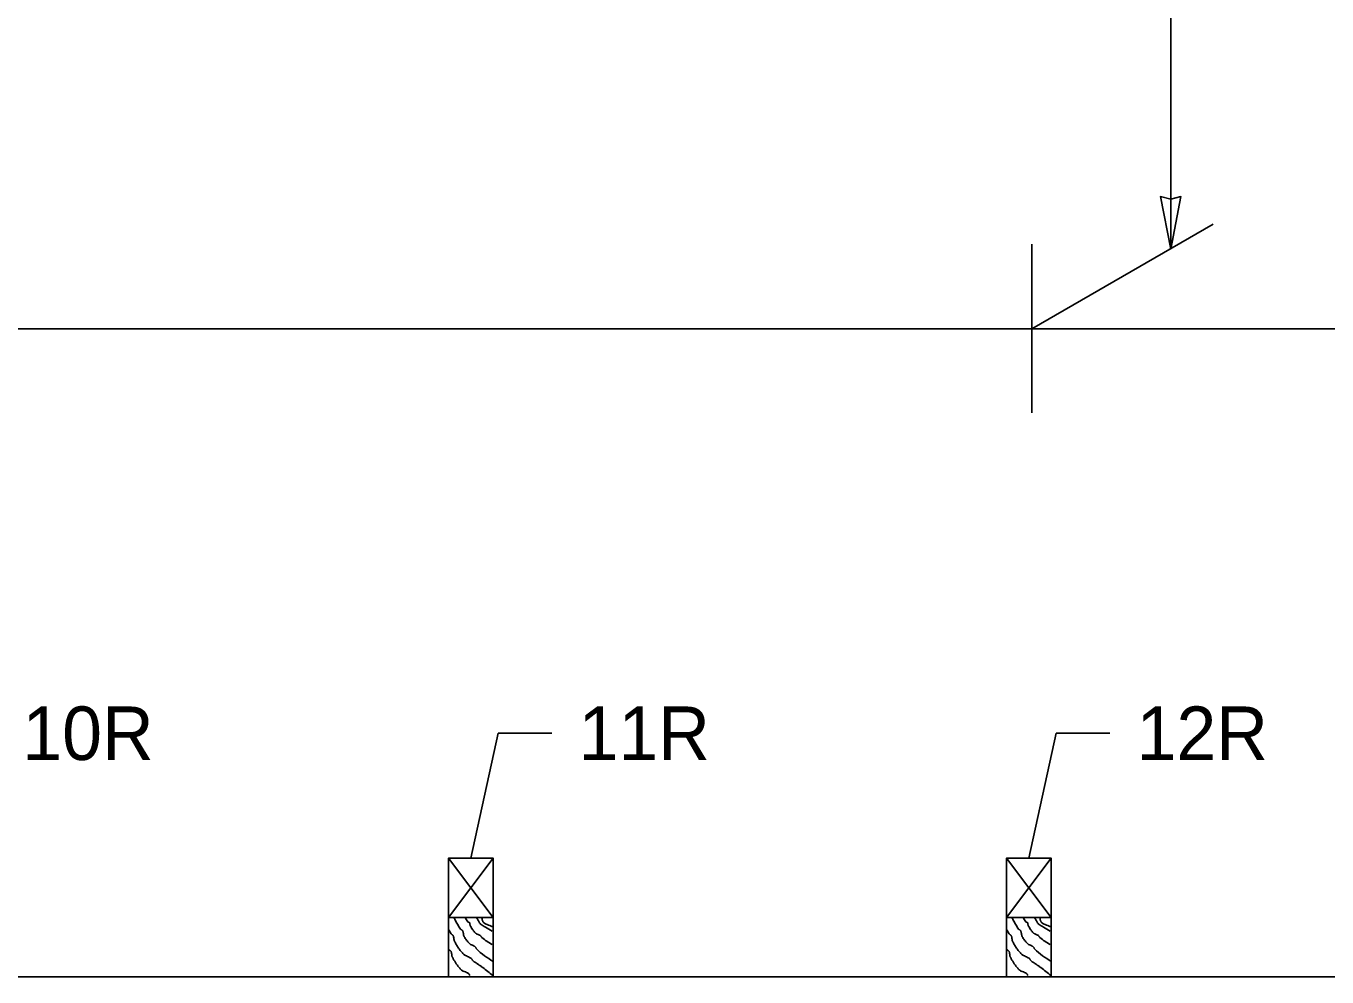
# Model space of a CAD drawing. Extents: x 1312564.2 to 1312581.5, y 1207298.4 to 1207352.6.
# Drawn here: x 1312571.742 to 1312573.678, y 1207306.026 to 1207307.442 of the extents above; entities that cross this region are included whole.
import ezdxf

# ---------------------------------------------------------------- set-up
doc = ezdxf.new("R2010")
doc.units = 0
for name, color, linetype in [('Level 13', 7, 'Continuous'), ('Level 14', 7, 'Continuous'), ('Level 15', 7, 'Continuous'), ('Level 20', 7, 'Continuous')]:
    doc.layers.add(name, color=color, linetype=linetype)

msp = doc.modelspace()

# ---------------------------------------------------------------- linework, layer by layer
at = {"layer": 'Level 13'}
for points in [[(1312572.3785139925, 1207306.1144906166), (1312572.3812686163, 1207306.1093584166), (1312572.3829368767, 1207306.1063364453), (1312572.3846655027, 1207306.1033469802), (1312572.3864358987, 1207306.1003835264), (1312572.388229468, 1207306.0974395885), (1312572.3885123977, 1207306.0970950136), (1312572.3888703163, 1207306.096820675), (1312572.3897133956, 1207306.0963912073), (1312572.3905632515, 1207306.0959681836), (1312572.3912244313, 1207306.0953686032), (1312572.391532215, 1207306.094851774), (1312572.391786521, 1207306.0943095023), (1312572.3921640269, 1207306.0931621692), (1312572.3925999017, 1207306.0907110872), (1312572.393001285, 1207306.0882319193), (1312572.393561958, 1207306.0864843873), (1312572.393837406, 1207306.0859412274), (1312572.3954116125, 1207306.0833483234), (1312572.397141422, 1207306.0808527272), (1312572.399039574, 1207306.0784748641), (1312572.4011188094, 1207306.0762351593), (1312572.4022092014, 1207306.07531773), (1312572.4034186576, 1207306.0745558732), (1312572.4060287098, 1207306.073294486), (1312572.408616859, 1207306.072042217), (1312572.4097989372, 1207306.0712917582), (1312572.4108509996, 1207306.0703902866), (1312572.4112330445, 1207306.0697751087), (1312572.4114778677, 1207306.0690462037), (1312572.4117438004, 1207306.068335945), (1312572.4121891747, 1207306.0677767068), (1312572.4370145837, 1207306.0492125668)], [(1312572.395383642, 1207306.1144906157), (1312572.3993067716, 1207306.1079405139), (1312572.3995254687, 1207306.1077062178), (1312572.39981993, 1207306.1075601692), (1312572.4005369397, 1207306.1074167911), (1312572.4012593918, 1207306.1072783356), (1312572.4017888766, 1207306.106912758), (1312572.40192999, 1207306.1066689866), (1312572.4020432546, 1207306.1064129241), (1312572.4022013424, 1207306.1058704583), (1312572.402349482, 1207306.1047099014), (1312572.4024749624, 1207306.1035356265), (1312572.4026047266, 1207306.102976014), (1312572.402819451, 1207306.102452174), (1312572.4036161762, 1207306.100979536), (1312572.4044412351, 1207306.0995169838), (1312572.4062161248, 1207306.096656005), (1312572.4093395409, 1207306.092651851), (1312572.4099298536, 1207306.0920315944), (1312572.4105434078, 1207306.091427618), (1312572.4114092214, 1207306.0907394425), (1312572.4123641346, 1207306.090189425), (1312572.41441809, 1207306.0893272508), (1312572.4164589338, 1207306.088487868), (1312572.4178327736, 1207306.0876608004), (1312572.4180402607, 1207306.0874944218), (1312572.4182403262, 1207306.087318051), (1312572.418771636, 1207306.086660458), (1312572.4192132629, 1207306.0859046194), (1312572.4196782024, 1207306.0851715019), (1312572.42027945, 1207306.0845820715), (1312572.4354167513, 1207306.074364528)], [(1312572.4122130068, 1207306.1144906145), (1312572.413608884, 1207306.1121563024), (1312572.4139176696, 1207306.1116223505), (1312572.4142171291, 1207306.111074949), (1312572.415997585, 1207306.1077201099), (1312572.4174041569, 1207306.1056941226), (1312572.4192258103, 1207306.104119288), (1312572.425366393, 1207306.1004058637), (1312572.435587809, 1207306.0942246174)], [(1312572.4201862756, 1207306.1144906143), (1312572.4204525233, 1207306.1127147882), (1312572.4207631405, 1207306.110974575), (1312572.4212449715, 1207306.1093717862), (1312572.4215897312, 1207306.1086537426), (1312572.4217950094, 1207306.108321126), (1312572.4219067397, 1207306.1081621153), (1312572.4219649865, 1207306.108084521), (1312572.4219947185, 1207306.108046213), (1312572.4220097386, 1207306.108027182), (1312572.422024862, 1207306.1080082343), (1312572.4223070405, 1207306.1076755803), (1312572.4226070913, 1207306.1073572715), (1312572.423257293, 1207306.1067608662), (1312572.4247334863, 1207306.105709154), (1312572.4281921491, 1207306.1040120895), (1312572.4319508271, 1207306.1025558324), (1312572.4338020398, 1207306.101805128), (1312572.4355594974, 1207306.1009791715)], [(1312573.2092494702, 1207306.1144906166), (1312573.2120040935, 1207306.1093584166), (1312573.2136723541, 1207306.1063364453), (1312573.2154009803, 1207306.1033469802), (1312573.2171713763, 1207306.1003835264), (1312573.2189649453, 1207306.0974395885), (1312573.219247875, 1207306.0970950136), (1312573.2196057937, 1207306.096820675), (1312573.2204488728, 1207306.0963912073), (1312573.221298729, 1207306.0959681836), (1312573.2219599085, 1207306.0953686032), (1312573.2222676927, 1207306.094851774), (1312573.2225219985, 1207306.0943095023), (1312573.2228995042, 1207306.0931621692), (1312573.223335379, 1207306.0907110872), (1312573.223736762, 1207306.0882319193), (1312573.2242974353, 1207306.0864843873), (1312573.2245728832, 1207306.0859412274), (1312573.22614709, 1207306.0833483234), (1312573.2278768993, 1207306.0808527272), (1312573.2297750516, 1207306.0784748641), (1312573.2318542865, 1207306.0762351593), (1312573.2329446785, 1207306.07531773), (1312573.234154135, 1207306.0745558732), (1312573.236764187, 1207306.073294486), (1312573.2393523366, 1207306.072042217), (1312573.2405344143, 1207306.0712917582), (1312573.2415864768, 1207306.0703902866), (1312573.2419685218, 1207306.0697751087), (1312573.2422133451, 1207306.0690462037), (1312573.2424792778, 1207306.068335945), (1312573.2429246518, 1207306.0677767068), (1312573.2677500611, 1207306.0492125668)], [(1312573.2261191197, 1207306.1144906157), (1312573.2300422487, 1207306.1079405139), (1312573.230260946, 1207306.1077062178), (1312573.2305554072, 1207306.1075601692), (1312573.2312724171, 1207306.1074167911), (1312573.231994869, 1207306.1072783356), (1312573.232524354, 1207306.106912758), (1312573.2326654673, 1207306.1066689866), (1312573.232778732, 1207306.1064129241), (1312573.2329368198, 1207306.1058704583), (1312573.2330849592, 1207306.1047099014), (1312573.2332104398, 1207306.1035356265), (1312573.2333402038, 1207306.102976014), (1312573.2335549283, 1207306.102452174), (1312573.2343516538, 1207306.100979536), (1312573.2351767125, 1207306.0995169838), (1312573.2369516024, 1207306.096656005), (1312573.240075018, 1207306.092651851), (1312573.240665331, 1207306.0920315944), (1312573.2412788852, 1207306.091427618), (1312573.2421446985, 1207306.0907394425), (1312573.243099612, 1207306.090189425), (1312573.245153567, 1207306.0893272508), (1312573.247194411, 1207306.088487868), (1312573.2485682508, 1207306.0876608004), (1312573.248775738, 1207306.0874944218), (1312573.2489758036, 1207306.087318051), (1312573.2495071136, 1207306.086660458), (1312573.2499487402, 1207306.0859046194), (1312573.2504136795, 1207306.0851715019), (1312573.2510149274, 1207306.0845820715), (1312573.2661522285, 1207306.074364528)], [(1312573.2429484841, 1207306.1144906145), (1312573.2443443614, 1207306.1121563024), (1312573.2446531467, 1207306.1116223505), (1312573.2449526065, 1207306.111074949), (1312573.2467330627, 1207306.1077201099), (1312573.2481396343, 1207306.1056941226), (1312573.2499612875, 1207306.104119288), (1312573.2561018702, 1207306.1004058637), (1312573.2663232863, 1207306.0942246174)], [(1312573.250921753, 1207306.1144906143), (1312573.251188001, 1207306.1127147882), (1312573.2514986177, 1207306.110974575), (1312573.251980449, 1207306.1093717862), (1312573.2523252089, 1207306.1086537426), (1312573.2525304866, 1207306.108321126), (1312573.2526422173, 1207306.1081621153), (1312573.2527004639, 1207306.108084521), (1312573.2527301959, 1207306.108046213), (1312573.2527452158, 1207306.108027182), (1312573.252760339, 1207306.1080082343), (1312573.2530425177, 1207306.1076755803), (1312573.2533425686, 1207306.1073572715), (1312573.2539927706, 1207306.1067608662), (1312573.2554689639, 1207306.105709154), (1312573.2589276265, 1207306.1040120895), (1312573.2626863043, 1207306.1025558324), (1312573.264537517, 1207306.101805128), (1312573.2662949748, 1207306.1009791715)], [(1312572.3705385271, 1207306.0969881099), (1312572.3745098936, 1207306.090235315), (1312572.375124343, 1207306.0895276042), (1312572.3758998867, 1207306.0889505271), (1312572.3766813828, 1207306.0883786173), (1312572.377313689, 1207306.0876864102), (1312572.377809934, 1207306.0867074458), (1312572.3781402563, 1207306.085656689), (1312572.3785089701, 1207306.0834245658), (1312572.3788315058, 1207306.0811595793), (1312572.3792907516, 1207306.0795412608), (1312572.3795195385, 1207306.0790312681), (1312572.3822477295, 1207306.0739511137), (1312572.3852974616, 1207306.0690740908), (1312572.38875612, 1207306.0644630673), (1312572.3906661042, 1207306.062276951), (1312572.3916710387, 1207306.0612171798), (1312572.392711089, 1207306.0601809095), (1312572.3940515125, 1207306.0590807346), (1312572.3955238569, 1207306.0581765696), (1312572.398682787, 1207306.05670616), (1312572.4018248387, 1207306.0552694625), (1312572.40395191, 1207306.0539131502), (1312572.4045869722, 1207306.0533662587), (1312572.4052531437, 1207306.0525585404), (1312572.4058191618, 1207306.051642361), (1312572.4064063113, 1207306.0507451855), (1312572.407135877, 1207306.049994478), (1312572.4106993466, 1207306.0474684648), (1312572.4143556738, 1207306.0450583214), (1312572.4180012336, 1207306.04262955), (1312572.421532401, 1207306.040047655), (1312572.4364246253, 1207306.0283428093)], [(1312573.2012740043, 1207306.0969881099), (1312573.2052453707, 1207306.090235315), (1312573.2058598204, 1207306.0895276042), (1312573.206635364, 1207306.0889505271), (1312573.2074168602, 1207306.0883786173), (1312573.2080491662, 1207306.0876864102), (1312573.2085454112, 1207306.0867074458), (1312573.2088757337, 1207306.085656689), (1312573.2092444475, 1207306.0834245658), (1312573.2095669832, 1207306.0811595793), (1312573.2100262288, 1207306.0795412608), (1312573.210255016, 1207306.0790312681), (1312573.2129832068, 1207306.0739511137), (1312573.216032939, 1207306.0690740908), (1312573.2194915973, 1207306.0644630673), (1312573.2214015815, 1207306.062276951), (1312573.222406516, 1207306.0612171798), (1312573.2234465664, 1207306.0601809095), (1312573.22478699, 1207306.0590807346), (1312573.226259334, 1207306.0581765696), (1312573.2294182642, 1207306.05670616), (1312573.2325603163, 1207306.0552694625), (1312573.2346873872, 1207306.0539131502), (1312573.2353224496, 1207306.0533662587), (1312573.2359886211, 1207306.0525585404), (1312573.2365546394, 1207306.051642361), (1312573.2371417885, 1207306.0507451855), (1312573.2378713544, 1207306.049994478), (1312573.241434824, 1207306.0474684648), (1312573.245091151, 1207306.0450583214), (1312573.2487367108, 1207306.04262955), (1312573.2522678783, 1207306.040047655), (1312573.2671601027, 1207306.0283428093)], [(1312572.3705385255, 1207306.067953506), (1312572.3711860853, 1207306.066858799), (1312572.3714634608, 1207306.0664805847), (1312572.3718003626, 1207306.0661507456), (1312572.372575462, 1207306.0655735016), (1312572.3733568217, 1207306.0650016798), (1312572.3737015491, 1207306.0646786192), (1312572.3739898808, 1207306.064309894), (1312572.37448738, 1207306.0633314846), (1312572.374818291, 1207306.0622809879), (1312572.3751868, 1207306.0600487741), (1312572.3755083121, 1207306.0577833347), (1312572.3757804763, 1207306.0566913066), (1312572.3761957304, 1207306.055654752), (1312572.3768531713, 1207306.0543695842), (1312572.3775279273, 1207306.0530949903), (1312572.3819995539, 1207306.0457138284), (1312572.3854614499, 1207306.0411048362), (1312572.3873621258, 1207306.0389128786), (1312572.3883586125, 1207306.037847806), (1312572.3893872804, 1207306.0368043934), (1312572.3907398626, 1207306.035722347), (1312572.3922648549, 1207306.0348767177), (1312572.3955626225, 1207306.0335534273), (1312572.3987416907, 1207306.0321519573), (1312572.4001183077, 1207306.0312086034), (1312572.401263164, 1207306.0299897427), (1312572.402354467, 1207306.028409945)], [(1312573.201274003, 1207306.067953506), (1312573.201921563, 1207306.066858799), (1312573.2021989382, 1207306.0664805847), (1312573.2025358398, 1207306.0661507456), (1312573.2033109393, 1207306.0655735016), (1312573.2040922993, 1207306.0650016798), (1312573.2044370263, 1207306.0646786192), (1312573.2047253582, 1207306.064309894), (1312573.2052228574, 1207306.0633314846), (1312573.2055537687, 1207306.0622809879), (1312573.2059222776, 1207306.0600487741), (1312573.2062437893, 1207306.0577833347), (1312573.2065159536, 1207306.0566913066), (1312573.2069312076, 1207306.055654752), (1312573.2075886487, 1207306.0543695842), (1312573.208263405, 1207306.0530949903), (1312573.2127350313, 1207306.0457138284), (1312573.2161969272, 1207306.0411048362), (1312573.2180976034, 1207306.0389128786), (1312573.2190940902, 1207306.037847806), (1312573.220122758, 1207306.0368043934), (1312573.22147534, 1207306.035722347), (1312573.223000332, 1207306.0348767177), (1312573.2262981, 1207306.0335534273), (1312573.2294771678, 1207306.0321519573), (1312573.2308537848, 1207306.0312086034), (1312573.231998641, 1207306.0299897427), (1312573.2330899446, 1207306.028409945)]]:
    msp.add_spline(points, degree=3, dxfattribs=at)
at = {"layer": 'Level 14'}
for p, q in [((1312572.4368627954, 1207306.1144906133), (1312572.3705385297, 1207306.2029671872)), ((1312572.3705385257, 1207306.114490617), (1312572.4368627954, 1207306.202967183)), ((1312573.2012740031, 1207306.114490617), (1312573.2675982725, 1207306.202967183)), ((1312573.2675982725, 1207306.1144906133), (1312573.2012740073, 1207306.2029671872))]:
    msp.add_line(p, q, dxfattribs=at)
at = {"layer": 'Level 15'}
for p, q in [((1312573.4455654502, 1207307.1095576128), (1312573.4455654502, 1207308.1116155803)), ((1312573.508918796, 1207307.146894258), (1312573.2386486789, 1207306.9908537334)), ((1312573.2386486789, 1207307.1169932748), (1312573.2386486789, 1207306.8658222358)), ((1312565.7519709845, 1207306.9908537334), (1312575.0870337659, 1207306.9908537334)), ((1312572.4445014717, 1207306.388906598), (1312572.4037006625, 1207306.2029671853)), ((1312572.5242301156, 1207306.388906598), (1312572.4445014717, 1207306.388906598)), ((1312573.275236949, 1207306.388906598), (1312573.2344361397, 1207306.2029671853)), ((1312573.3549655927, 1207306.388906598), (1312573.275236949, 1207306.388906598)), ((1312568.2576711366, 1207306.0263555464), (1312575.0870337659, 1207306.0263555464))]:
    msp.add_line(p, q, dxfattribs=at)
for points in [[(1312573.4455654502, 1207307.1095576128), (1312573.4609331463, 1207307.1879159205), (1312573.4455654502, 1207307.1842882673), (1312573.4301977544, 1207307.1879159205)], [(1312572.3705385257, 1207306.114490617), (1312572.4368627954, 1207306.1144906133), (1312572.4368627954, 1207306.202967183), (1312572.3705385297, 1207306.2029671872)], [(1312573.2012740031, 1207306.114490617), (1312573.2675982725, 1207306.1144906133), (1312573.2675982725, 1207306.202967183), (1312573.2012740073, 1207306.2029671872)], [(1312572.3705385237, 1207306.026014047), (1312572.4368627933, 1207306.026014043), (1312572.4368627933, 1207306.1144906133), (1312572.3705385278, 1207306.114490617)], [(1312573.201274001, 1207306.026014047), (1312573.2675982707, 1207306.026014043), (1312573.2675982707, 1207306.1144906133), (1312573.2012740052, 1207306.114490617)]]:
    msp.add_lwpolyline(points, close=True, dxfattribs=at)

# ---------------------------------------------------------------- texts
at = {"layer": 'Level 20'}
for s, p in [('10R', (1312571.7360444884, 1207306.3490422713)), ('12R', (1312573.3948299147, 1207306.3490422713)), ('11R', (1312572.564094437, 1207306.3490422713))]:
    msp.add_text(s, height=0.07972865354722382, dxfattribs=at).set_placement(p)

doc.saveas('drawing.dxf')
